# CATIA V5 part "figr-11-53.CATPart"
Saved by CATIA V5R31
Part number: Part1
Bounding box of the stored display mesh (mm): x -70 to 82, y -87.905 to 70, z 0 to 79.806
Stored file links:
  D:\PROJECTS\Project 2021\US EDITION\CATIA V5 6R 2021\Resources\Part Files\c11_catia_v5_6r2021_prt\figr-11-53.CATPart
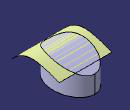
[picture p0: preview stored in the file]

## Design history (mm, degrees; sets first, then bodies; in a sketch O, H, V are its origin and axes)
Set1
  Extrude1: Element1 Sketch2, Lim1 82, Lim2 70, Direction yz-plane
Body1 (main body)
  Sketch1 on xy-plane, origin (0, 0, 0), H (1, 0, 0), V (0, 1, 0)
    ellipse A1 centre (0, 0) semi-axes 70, 50 rotation 90
    point P1 (50, 0)
    coincidence: P1 H, A1 P1
  Pad1: profile Sketch1, direction (0, 0, 1), length 84
  Split1: SplitPlane Extrude1
  Sketch2 on yz-plane, origin (0, 0, 0), H (0, 1, 0), V (0, 0, 1)
    spline S1 through (-87.9047, 49.8062) (-27.9047, 79.8062) (23.1382, 69.0456) (49.2374, 59.3792)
